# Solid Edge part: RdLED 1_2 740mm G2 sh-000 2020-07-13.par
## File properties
Author: sylwester.cabaj
Template: iso metric part.par
Last saved by: sylwester.cabaj
Revision: 2
Application: Solid Edge
Gęstość: 0,000 kg/m^3
Dokładność: 0,990
Username: sylwester.cabaj
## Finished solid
Body 1: solid body, 5631 faces, 14708 edges, 9674 vertices.
  Faces by surface: plane 5124, cylinder 239, spline 160, cone 52, torus 22, sphere 20, spun 14
  Edges by curve: line 13608, curve on surface 564, circle 316, ellipse 132, spline 76, intersection 12
Bounding box of the edges (mm; curved faces can reach further): 716.000 x 4.450 x 355.500, from (-358, -3.45, -177.75) to (358, 1, 177.75).
Cylindrical faces by radius (mm): R0.2 x78, R0.2002 x4, R0.2169 x6, R0.25 x24, R0.3 x4, R0.3373 x6, R0.4 x16, R0.4006 x4, R0.4008 x4, R0.525 x4, R0.6 x24, R1 x14, R1.0894 x4, R1.1 x28, R2 x2, R2.25 x15, R370 x2
Conical faces (half-angle, radius in mm at the cone's reference point): 0.5 deg R0.5056 x8, 0.5 deg R1.0082 x8, 1 deg R0.5511 x4, 10 deg R0.2132 x4, 10 deg R0.4132 x4, 18.4844 deg R1.0657 x8, 27.363 deg R0.6214 x4, 45 deg R0.575 x4, 45 deg R0.625 x8
Toroidal faces (ring radius, tube radius in mm): R0.1 r0.2 x2, R0.8 r0.2 x8, R0.8522 r0.3 x4, R0.9002 r0.2 x2, R0.9018 r0.2 x2, R1.3 r0.2 x4
Spherical faces by radius (mm): R0.2 x16, R0.6 x4
Planar faces by outward normal: +x 44, +y 15, +z 43, -x 38, -y 939, -z 37, oblique 4008
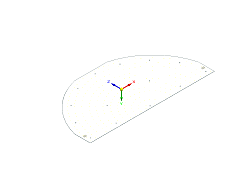
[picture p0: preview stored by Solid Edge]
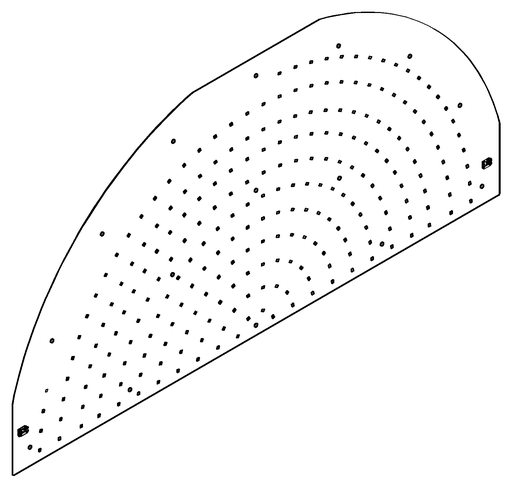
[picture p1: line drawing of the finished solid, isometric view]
